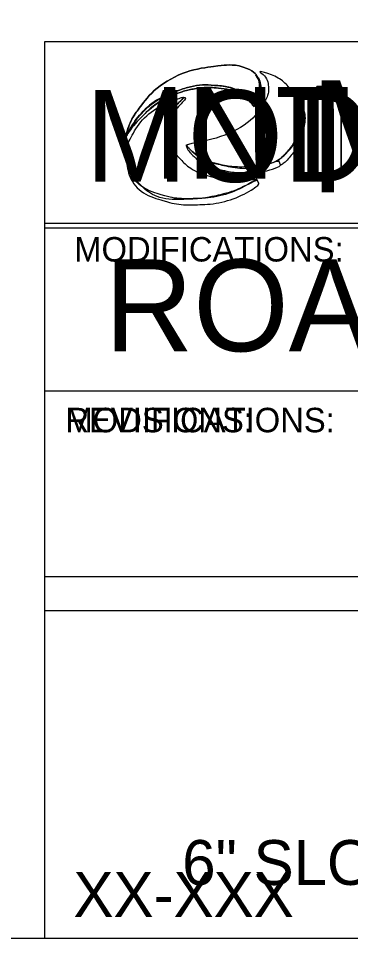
# Model space of a CAD drawing. Extents: x 10133 to 81668, y 2357 to 12713.
# Drawn here: x 12684.8 to 12847.5, y 4251.2 to 4702.6 of the extents above; entities that cross this region are included whole.
import ezdxf

# ---------------------------------------------------------------- set-up
doc = ezdxf.new("R2010")
doc.units = 0
for name, color, linetype in [('dsnDOTLogo', 7, 'Continuous'), ('dsnNonPlotable', 7, 'Continuous'), ('dsnStdBlock', 7, 'Continuous'), ('dsnStdBlockInterim', 7, 'Continuous'), ('dsnStdBlockModified', 7, 'Continuous'), ('dsnStdBorder', 7, 'Continuous'), ('dsnstdModifiedBlock', 7, 'Continuous'), ('SheetRevisedText', 7, 'Continuous')]:
    doc.layers.add(name, color=color, linetype=linetype)

msp = doc.modelspace()

# ---------------------------------------------------------------- linework, layer by layer
at = {"layer": 'dsnDOTLogo'}
for p, q in [((12799.24, 4661.45), (12798.91, 4661.8)), ((12798.91, 4661.8), (12799.24, 4661.45)), ((12799.54, 4661.82), (12799.24, 4661.45)), ((12799.24, 4661.45), (12799.54, 4661.82)), ((12800.07, 4659.28), (12800.13, 4659.35)), ((12800.13, 4659.35), (12800.32, 4659.59)), ((12800.5, 4659.8), (12800.59, 4659.92)), ((12800.59, 4659.92), (12800.59, 4659.93)), ((12800.79, 4660.22), (12800.8, 4660.22)), ((12800.8, 4660.22), (12800.8, 4660.23)), ((12744.69, 4653.75), (12744.69, 4653.74)), ((12738.19, 4647.91), (12736.99, 4644.36)), ((12738.95, 4647.56), (12736.99, 4644.36)), ((12736.99, 4644.36), (12738.95, 4647.56)), ((12736.99, 4644.36), (12736.99, 4643.95))]:
    msp.add_line(p, q, dxfattribs=at)
for points in [[(12842.91, 4624.93), (12842.91, 4669.23), (12830.97, 4669.23), (12830.97, 4624.93), (12842.91, 4624.93)], [(12842.91, 4669.23), (12842.91, 4624.93), (12830.97, 4624.93), (12830.97, 4669.23), (12842.91, 4669.23)]]:
    msp.add_lwpolyline(points, dxfattribs=at)
for points, degree in [([(12792.9, 4679.23), (12790.27, 4679.78), (12786.53, 4679.8), (12782.13, 4679.26), (12766.95, 4677.26), (12751.46, 4668.74), (12743.6, 4658.06), (12741.19, 4654.79), (12739.37, 4651.37), (12738.19, 4647.91), (12738.19, 4647.91), (12736.99, 4644.36), (12736.99, 4644.36), (12736.99, 4644.36), (12738.95, 4647.56), (12738.95, 4647.56), (12744.35, 4656.36), (12753.51, 4663.73), (12763.45, 4667.26), (12769.05, 4669.26), (12775.02, 4670.13), (12780.47, 4669.75), (12787.94, 4669.23), (12794.66, 4666.33), (12798.91, 4661.8), (12798.91, 4661.8), (12799.24, 4661.45), (12799.24, 4661.45), (12799.24, 4661.45), (12799.54, 4661.82), (12799.54, 4661.82), (12800.21, 4662.63), (12800.78, 4663.44), (12801.24, 4664.21), (12802.41, 4666.2), (12802.96, 4668.17), (12802.85, 4670.09), (12802.43, 4674.31), (12798.81, 4677.64), (12792.9, 4679.23)], 3), ([(12792.9, 4679.23), (12790.27, 4679.78), (12786.53, 4679.8), (12782.13, 4679.26), (12766.95, 4677.26), (12751.46, 4668.74), (12743.6, 4658.06), (12741.19, 4654.79), (12739.37, 4651.37), (12738.19, 4647.91)], 3), ([(12822.5, 4647.25), (12820.69, 4642.1), (12817.19, 4637.26), (12812.4, 4632.94), (12803.33, 4629.36), (12793.04, 4628.69), (12783.94, 4630.76), (12777.81, 4632.15), (12772.51, 4634.75), (12768.73, 4638.51), (12767.97, 4639.26), (12767.31, 4640.03), (12766.72, 4640.84), (12783.9, 4643.58), (12800.08, 4652.23), (12805.71, 4662.46), (12806.94, 4664.71), (12807.41, 4666.89), (12807.19, 4668.91), (12806.97, 4672.26), (12804.89, 4675.17), (12801.32, 4677.2), (12808.95, 4675.23), (12815.11, 4671.49), (12818.94, 4666.94), (12821.6, 4663.78), (12823.26, 4660.01), (12823.67, 4655.95), (12823.89, 4653.16), (12823.53, 4650.23), (12822.5, 4647.25)], 3), ([(12822.5, 4647.25), (12820.69, 4642.1), (12817.19, 4637.26), (12812.4, 4632.94), (12803.33, 4629.36), (12793.04, 4628.69), (12783.94, 4630.76), (12777.81, 4632.15), (12772.51, 4634.75), (12768.73, 4638.51), (12767.97, 4639.26), (12767.31, 4640.03), (12766.72, 4640.84), (12783.9, 4643.58), (12800.08, 4652.23), (12805.71, 4662.46), (12806.94, 4664.71), (12807.41, 4666.89), (12807.19, 4668.91), (12806.97, 4672.26), (12804.89, 4675.17), (12801.32, 4677.2), (12808.95, 4675.23), (12815.11, 4671.49), (12818.94, 4666.94), (12821.6, 4663.78), (12823.26, 4660.01), (12823.67, 4655.95), (12823.89, 4653.16), (12823.53, 4650.23), (12822.5, 4647.25)], 3), ([(12799.54, 4661.82), (12800.21, 4662.63), (12800.78, 4663.44), (12801.24, 4664.21), (12802.41, 4666.2), (12802.96, 4668.17), (12802.85, 4670.09), (12802.43, 4674.31), (12798.81, 4677.64), (12792.9, 4679.23)], 3), ([(12803.37, 4670.13), (12803.37, 4670.13), (12802.99, 4672.86), (12800.17, 4675.41), (12801.72, 4673.9), (12802.65, 4672.09), (12802.85, 4670.09), (12802.96, 4668.17), (12802.41, 4666.2), (12801.24, 4664.21), (12800.78, 4663.44), (12800.21, 4662.63), (12799.54, 4661.82), (12799.54, 4661.82), (12799.24, 4661.45), (12799.24, 4661.45), (12799.24, 4661.45), (12798.91, 4661.8), (12798.91, 4661.8), (12794.66, 4666.33), (12787.94, 4669.23), (12780.47, 4669.75), (12775.02, 4670.13), (12769.05, 4669.26), (12763.45, 4667.26), (12753.51, 4663.73), (12744.35, 4656.36), (12738.95, 4647.56), (12738.95, 4647.56), (12736.99, 4644.36), (12736.99, 4644.36), (12736.99, 4644.36), (12736.99, 4643.95), (12736.99, 4643.95), (12736.99, 4643.95), (12741.29, 4650.5), (12744.69, 4653.75), (12744.69, 4653.75), (12744.69, 4653.74), (12744.69, 4653.74), (12749.8, 4659.09), (12756.39, 4663.57), (12763.67, 4666.12), (12766.36, 4667.06), (12769.04, 4667.73), (12771.67, 4668.14), (12774.96, 4668.65), (12778.18, 4668.76), (12781.24, 4668.5), (12786.91, 4668.03), (12792.12, 4666.23), (12796.27, 4663.37), (12796.69, 4663.04), (12798.59, 4661.49), (12800.07, 4659.28), (12800.07, 4659.28), (12800.13, 4659.35), (12800.13, 4659.35), (12800.13, 4659.35), (12800.32, 4659.59), (12800.32, 4659.59), (12800.33, 4659.58), (12800.33, 4659.58), (12800.33, 4659.58), (12800.39, 4659.65), (12800.44, 4659.73), (12800.5, 4659.8), (12800.5, 4659.8), (12800.59, 4659.92), (12800.59, 4659.92), (12800.59, 4659.92), (12800.59, 4659.93), (12800.59, 4659.93), (12800.66, 4660.03), (12800.73, 4660.13), (12800.79, 4660.22), (12800.79, 4660.22), (12800.8, 4660.22), (12800.8, 4660.22), (12800.8, 4660.22), (12800.8, 4660.23), (12800.8, 4660.23), (12801.24, 4660.85), (12801.65, 4661.47), (12801.99, 4662.1), (12803.59, 4664.98), (12804.01, 4667.72), (12803.37, 4670.13)], 3), ([(12803.37, 4670.13), (12803.37, 4670.13), (12802.99, 4672.86), (12800.17, 4675.41), (12801.72, 4673.9), (12802.65, 4672.09), (12802.85, 4670.09), (12802.96, 4668.17), (12802.41, 4666.2), (12801.24, 4664.21), (12800.78, 4663.44), (12800.21, 4662.63), (12799.54, 4661.82)], 3), ([(12798.91, 4661.8), (12794.66, 4666.33), (12787.94, 4669.23), (12780.47, 4669.75), (12775.02, 4670.13), (12769.05, 4669.26), (12763.45, 4667.26), (12753.51, 4663.73), (12744.35, 4656.36), (12738.95, 4647.56)], 3), ([(12738.95, 4647.56), (12744.35, 4656.36), (12753.51, 4663.73), (12763.45, 4667.26), (12769.05, 4669.26), (12775.02, 4670.13), (12780.47, 4669.75), (12787.94, 4669.23), (12794.66, 4666.33), (12798.91, 4661.8)], 3), ([(12744.69, 4653.74), (12749.8, 4659.09), (12756.39, 4663.57), (12763.67, 4666.12), (12766.36, 4667.06), (12769.04, 4667.73), (12771.67, 4668.14), (12774.96, 4668.65), (12778.18, 4668.76), (12781.24, 4668.5), (12786.91, 4668.03), (12792.12, 4666.23), (12796.27, 4663.37), (12796.69, 4663.04), (12798.59, 4661.49), (12800.07, 4659.28)], 3), ([(12800.8, 4660.23), (12801.24, 4660.85), (12801.65, 4661.47), (12801.99, 4662.1), (12803.59, 4664.98), (12804.01, 4667.72), (12803.37, 4670.13)], 3), ([(12812.23, 4632.96), (12812.63, 4632.06), (12813.02, 4631.13), (12813.41, 4630.21), (12818.15, 4634.72), (12821.59, 4639.75), (12823.32, 4645.09), (12825.79, 4652.72), (12824.19, 4660), (12819.75, 4665.58), (12819.34, 4666.1), (12818.93, 4666.61), (12818.52, 4667.1), (12822.93, 4661.79), (12824.53, 4654.8), (12822.1, 4647.45), (12820.38, 4642.27), (12816.94, 4637.37), (12812.23, 4632.96), (12812.23, 4632.96), (12812.23, 4632.96), (12812.23, 4632.96)], 3), ([(12812.23, 4632.96), (12812.63, 4632.06), (12813.02, 4631.13), (12813.41, 4630.21), (12818.15, 4634.72), (12821.59, 4639.75), (12823.32, 4645.09), (12825.79, 4652.72), (12824.19, 4660), (12819.75, 4665.58), (12819.34, 4666.1), (12818.93, 4666.61), (12818.52, 4667.1), (12822.93, 4661.79), (12824.53, 4654.8), (12822.1, 4647.45), (12820.38, 4642.27), (12816.94, 4637.37), (12812.23, 4632.96), (12812.23, 4632.96), (12812.23, 4632.96), (12812.23, 4632.96)], 3), ([(12781.31, 4624.42), (12774.34, 4626.04), (12768.37, 4629.06), (12764.18, 4633.42), (12760.72, 4637.03), (12758.88, 4641.31), (12758.58, 4645.72), (12758.03, 4652.06), (12760.68, 4658.72), (12766.27, 4664.15), (12765.23, 4663.88), (12764.19, 4663.56), (12763.15, 4663.19), (12753.18, 4659.66), (12743.96, 4652.07), (12739.11, 4642.58), (12736.74, 4637.93), (12737.23, 4632.57), (12739.42, 4627.95), (12740.13, 4626.44), (12741.05, 4624.79), (12742.16, 4623.53), (12746.25, 4618.84), (12754.27, 4613.35), (12769.24, 4613.94), (12770.27, 4613.98), (12771.35, 4614.06), (12772.45, 4614.15), (12772.45, 4614.15), (12775.22, 4614.28), (12779.58, 4615.17), (12779.64, 4615.18), (12779.71, 4615.19), (12779.78, 4615.21), (12779.78, 4615.21), (12779.87, 4615.23), (12780.03, 4615.27), (12784.91, 4616.3), (12791.61, 4618.25), (12798.59, 4621.95), (12799.66, 4622.5), (12800.7, 4623.08), (12801.7, 4623.69), (12801.7, 4623.69), (12787.43, 4623), (12781.31, 4624.42)], 3), ([(12781.31, 4624.42), (12774.34, 4626.04), (12768.37, 4629.06), (12764.18, 4633.42), (12760.72, 4637.03), (12758.88, 4641.31), (12758.58, 4645.72), (12758.03, 4652.06), (12760.68, 4658.72), (12766.27, 4664.15), (12765.23, 4663.88), (12764.19, 4663.56), (12763.15, 4663.19), (12753.18, 4659.66), (12743.96, 4652.07), (12739.11, 4642.58), (12736.74, 4637.93), (12737.23, 4632.57), (12739.42, 4627.95), (12740.13, 4626.44), (12741.05, 4624.79), (12742.16, 4623.53), (12746.25, 4618.84), (12754.27, 4613.35), (12769.24, 4613.94), (12770.27, 4613.98), (12771.35, 4614.06), (12772.45, 4614.15), (12772.45, 4614.15), (12775.22, 4614.28), (12779.58, 4615.17), (12779.64, 4615.18), (12779.71, 4615.19), (12779.78, 4615.21), (12779.78, 4615.21), (12779.87, 4615.23), (12780.03, 4615.27), (12784.91, 4616.3), (12791.61, 4618.25), (12798.59, 4621.95), (12799.66, 4622.5), (12800.7, 4623.08), (12801.7, 4623.69), (12801.7, 4623.69), (12787.43, 4623), (12781.31, 4624.42)], 3), ([(12758.48, 4642.22), (12758.67, 4641.48), (12758.86, 4640.73), (12759.07, 4639.98), (12757.03, 4647.51), (12759.72, 4656.11), (12766.72, 4662.83), (12766.57, 4663.28), (12766.43, 4663.72), (12766.28, 4664.15), (12759.35, 4657.71), (12756.59, 4649.43), (12758.48, 4642.22), (12758.48, 4642.22), (12758.48, 4642.22), (12758.48, 4642.22)], 3), ([(12758.48, 4642.22), (12758.67, 4641.48), (12758.86, 4640.73), (12759.07, 4639.98), (12757.03, 4647.51), (12759.72, 4656.11), (12766.72, 4662.83), (12766.57, 4663.28), (12766.43, 4663.72), (12766.28, 4664.15), (12759.35, 4657.71), (12756.59, 4649.43), (12758.48, 4642.22), (12758.48, 4642.22), (12758.48, 4642.22), (12758.48, 4642.22)], 3), ([(12800.32, 4659.59), (12800.33, 4659.58), (12800.33, 4659.58), (12800.33, 4659.58), (12800.39, 4659.65), (12800.44, 4659.73), (12800.5, 4659.8)], 3), ([(12800.59, 4659.93), (12800.66, 4660.03), (12800.73, 4660.13), (12800.79, 4660.22)], 2), ([(12736.99, 4643.95), (12736.99, 4643.95), (12741.29, 4650.5), (12744.69, 4653.75)], 2), ([(12768.96, 4638.28), (12772.7, 4634.65), (12777.96, 4632.13), (12784.04, 4630.79), (12787.5, 4630.02), (12791.18, 4629.65), (12794.94, 4629.68), (12800.86, 4629.74), (12806.83, 4630.8), (12812.29, 4632.88), (12812.68, 4632), (12813.04, 4631.11), (12813.42, 4630.21), (12807.97, 4628.07), (12801.99, 4626.99), (12796.05, 4626.93), (12792.28, 4626.9), (12788.59, 4627.28), (12785.1, 4628.07), (12778.96, 4629.47), (12773.62, 4632.08), (12769.78, 4635.84), (12768.91, 4636.68), (12768.15, 4637.57), (12767.48, 4638.48), (12767.22, 4639.27), (12766.98, 4640.06), (12766.72, 4640.84), (12767.37, 4639.95), (12768.1, 4639.1), (12768.96, 4638.28)], 3), ([(12768.96, 4638.28), (12772.7, 4634.65), (12777.96, 4632.13), (12784.04, 4630.79), (12787.5, 4630.02), (12791.18, 4629.65), (12794.94, 4629.68), (12800.86, 4629.74), (12806.83, 4630.8), (12812.29, 4632.88), (12812.68, 4632), (12813.04, 4631.11), (12813.42, 4630.21), (12807.97, 4628.07), (12801.99, 4626.99), (12796.05, 4626.93), (12792.28, 4626.9), (12788.59, 4627.28), (12785.1, 4628.07), (12778.96, 4629.47), (12773.62, 4632.08), (12769.78, 4635.84), (12768.91, 4636.68), (12768.15, 4637.57), (12767.48, 4638.48), (12767.22, 4639.27), (12766.98, 4640.06), (12766.72, 4640.84), (12767.37, 4639.95), (12768.1, 4639.1), (12768.96, 4638.28)], 3), ([(12737.6, 4635.03), (12738.66, 4626.23), (12744.92, 4618.81), (12755.89, 4615.72), (12760.07, 4614.55), (12764.6, 4614.05), (12769.32, 4614.16), (12780.42, 4614.41), (12791.88, 4617.89), (12801.7, 4623.7), (12802.08, 4622.7), (12802.44, 4621.69), (12802.81, 4620.69), (12793, 4614.8), (12781.5, 4611.33), (12770.34, 4611.15), (12765.57, 4611.09), (12760.99, 4611.63), (12756.74, 4612.86), (12745.13, 4616.26), (12738.55, 4624.42), (12737.65, 4633.95), (12737.62, 4634.32), (12737.61, 4634.68), (12737.6, 4635.03)], 3), ([(12737.6, 4635.03), (12738.66, 4626.23), (12744.92, 4618.81), (12755.89, 4615.72), (12760.07, 4614.55), (12764.6, 4614.05), (12769.32, 4614.16), (12780.42, 4614.41), (12791.88, 4617.89), (12801.7, 4623.7), (12802.08, 4622.7), (12802.44, 4621.69), (12802.81, 4620.69), (12793, 4614.8), (12781.5, 4611.33), (12770.34, 4611.15), (12765.57, 4611.09), (12760.99, 4611.63), (12756.74, 4612.86), (12745.13, 4616.26), (12738.55, 4624.42), (12737.65, 4633.95), (12737.62, 4634.32), (12737.61, 4634.68), (12737.6, 4635.03)], 3)]:
    msp.add_open_spline(points, degree=degree, dxfattribs=at)
at = {"layer": 'dsnNonPlotable'}
msp.add_lwpolyline([(12697.77, 4691.26), (13385.79, 4691.26), (13385.79, 4251.25), (12697.77, 4251.25)], close=True, dxfattribs=at)
at = {"layer": 'dsnStdBlock'}
for p, q in [((12697.79, 4599.91), (13174.89, 4599.91)), ((12697.79, 4519.91), (13385.81, 4519.91)), ((12697.79, 4428.9), (13385.81, 4428.9))]:
    msp.add_line(p, q, dxfattribs=at)
msp.add_lwpolyline([(12697.79, 4691.25), (13385.81, 4691.25), (13385.81, 4251.24), (12697.79, 4251.24)], close=True, dxfattribs=at)
at = {"layer": 'dsnStdBorder'}
msp.add_lwpolyline([(10250.81, 6261.24), (13385.81, 6261.24), (13385.81, 4251.24), (10250.81, 4251.24)], close=True, dxfattribs=at)
at = {"layer": 'dsnstdModifiedBlock'}
for p, q in [((12697.79, 4602.16), (13385.81, 4602.16)), ((12697.79, 4412.15), (13385.81, 4412.15))]:
    msp.add_line(p, q, dxfattribs=at)
msp.add_lwpolyline([(12697.79, 4691.25), (13385.81, 4691.25), (13385.81, 4251.24), (12697.79, 4251.24)], close=True, dxfattribs=at)

# ---------------------------------------------------------------- texts
at = {"layer": 'dsnStdBlock'}
for s, height, p in [('ROAD DESIGN DETAIL', 45.0011, (12726.92, 4539.33)), ('6" SLOPED CURB AND GUTTER UNIT', 22, (12764.99, 4277.57))]:
    msp.add_text(s, height=height, dxfattribs=at).set_placement(p)
at = {"layer": 'dsnStdBlockInterim'}
msp.add_text('INTERIM', height=45.001, dxfattribs=at).set_placement((12750.46, 4623.97))
at = {"layer": 'dsnStdBlockModified'}
for s, height, p in [('MODIFIED', 45.001, (12717.49, 4622.41)), ('MODIFICATIONS:', 12, (12707.79, 4499.57))]:
    msp.add_text(s, height=height, dxfattribs=at).set_placement(p)
at = {"layer": 'dsnstdModifiedBlock'}
for s, height, p in [('MODIFIED', 55, (12827.2, 4617.25)), ('MODIFICATIONS:', 12, (12712.11, 4583.32)), ('XX-XXX', 22, (12711.72, 4261.87))]:
    msp.add_text(s, height=height, dxfattribs=at).set_placement(p)
at = {"layer": 'SheetRevisedText'}
msp.add_text('REVISIONS:', height=12, dxfattribs=at).set_placement((12707.79, 4499.57))

doc.saveas('drawing.dxf')
